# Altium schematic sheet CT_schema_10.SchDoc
size 385 x 385 mm
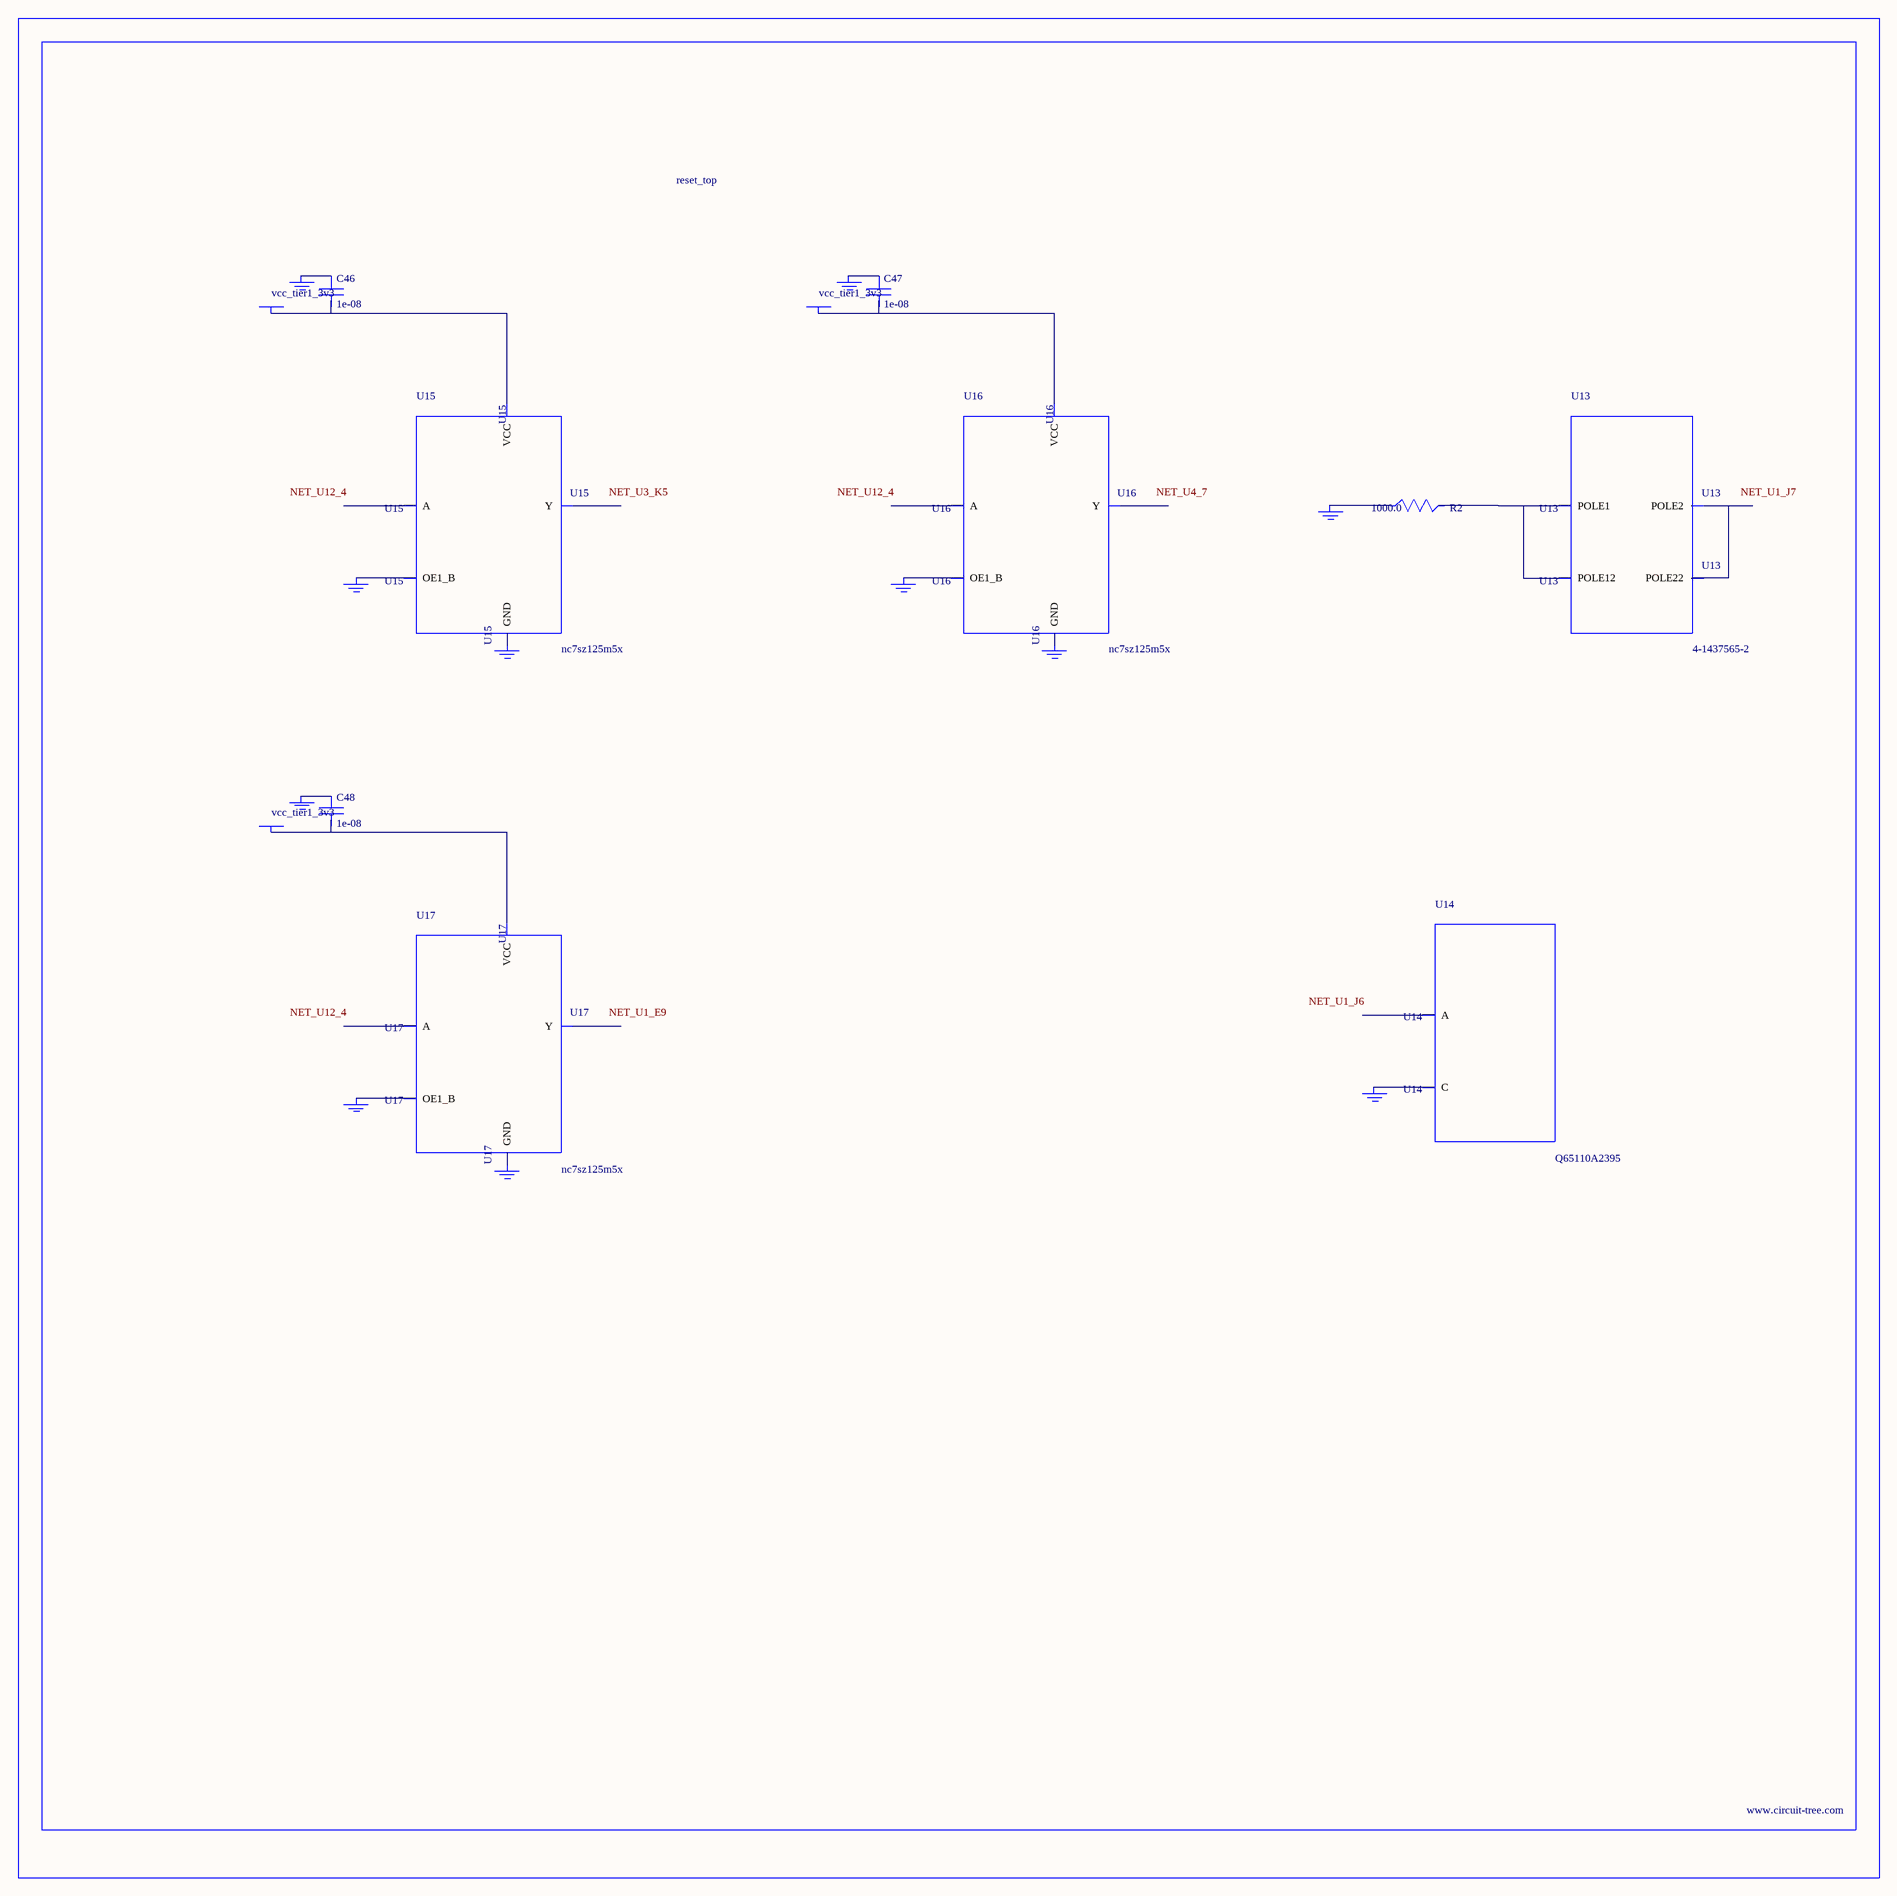
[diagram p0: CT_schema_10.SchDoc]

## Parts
BORDER9  (no value)
C46  1e-08  [C0402]
C47  1e-08  [C0402]
C48  1e-08  [C0402]
GND_INSTANCE_9_0  (no value)
GND_INSTANCE_9_1  (no value)
GND_INSTANCE_9_2  (no value)
GND_INSTANCE_9_3  (no value)
GND_INSTANCE_9_4  (no value)
GND_INSTANCE_9_5  (no value)
GND_INSTANCE_9_6  (no value)
GND_INSTANCE_9_7  (no value)
GND_INSTANCE_9_8  (no value)
GND_INSTANCE_9_9  (no value)
GND_INSTANCE_9_10  (no value)
POWER_INSTANCE_9_0  vcc_tier1_3v3
POWER_INSTANCE_9_1  vcc_tier1_3v3
POWER_INSTANCE_9_2  vcc_tier1_3v3
R2  1000.0  [R0603]
U13  4-1437565-2  [SW_4-1437565-2]
U14  Q65110A2395  [LGM67K-G1J2-24-Z]
U15  nc7sz125m5x  [NC7SZ125M5X]
U16  nc7sz125m5x  [NC7SZ125M5X]
U17  nc7sz125m5x  [NC7SZ125M5X]

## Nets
NetC46_1: C46.1 GND_INSTANCE_9_2.0(GND)
NetC46_2: C46.2 POWER_INSTANCE_9_0.0(PWR) U15.5(VCC)
NetC47_1: C47.1 GND_INSTANCE_9_5.0(GND)
NetC47_2: C47.2 POWER_INSTANCE_9_1.0(PWR) U16.5(VCC)
NetC48_1: C48.1 GND_INSTANCE_9_8.0(GND)
NetC48_2: C48.2 POWER_INSTANCE_9_2.0(PWR) U17.5(VCC)
NetGND_INSTANCE_9_0_0: GND_INSTANCE_9_0.0(GND) R2.1
NetGND_INSTANCE_9_1_0: GND_INSTANCE_9_1.0(GND) U14.C
NetGND_INSTANCE_9_3_0: GND_INSTANCE_9_3.0(GND) U15.1(OE1_B)
NetGND_INSTANCE_9_4_0: GND_INSTANCE_9_4.0(GND) U15.3(GND)
NetGND_INSTANCE_9_6_0: GND_INSTANCE_9_6.0(GND) U16.1(OE1_B)
NetGND_INSTANCE_9_7_0: GND_INSTANCE_9_7.0(GND) U16.3(GND)
NetGND_INSTANCE_9_9_0: GND_INSTANCE_9_9.0(GND) U17.1(OE1_B)
NetGND_INSTANCE_9_10_0: GND_INSTANCE_9_10.0(GND) U17.3(GND)
NetR2_2: R2.2 U13.1(POLE1) U13.2(POLE12)
NetU13_3: U13.3(POLE2) U13.4(POLE22)

Not connected (* = marked no-connect by the designer): U14 A; U15 2(A) 4(Y); U16 2(A) 4(Y); U17 2(A) 4(Y)

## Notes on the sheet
- Labels drawn without touching a wire or pin: NET_U1_E9, NET_U1_J6, NET_U1_J7, NET_U3_K5, NET_U4_7, NET_U12_4

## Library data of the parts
BORDER9 = BORDER_PAGE9
C46-C48 = C0402C103K3RAC
GND_INSTANCE_9_0-GND_INSTANCE_9_10 = GND
POWER_INSTANCE_9_0-POWER_INSTANCE_9_2 = PWR
R2 = RC0603JR-071KL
